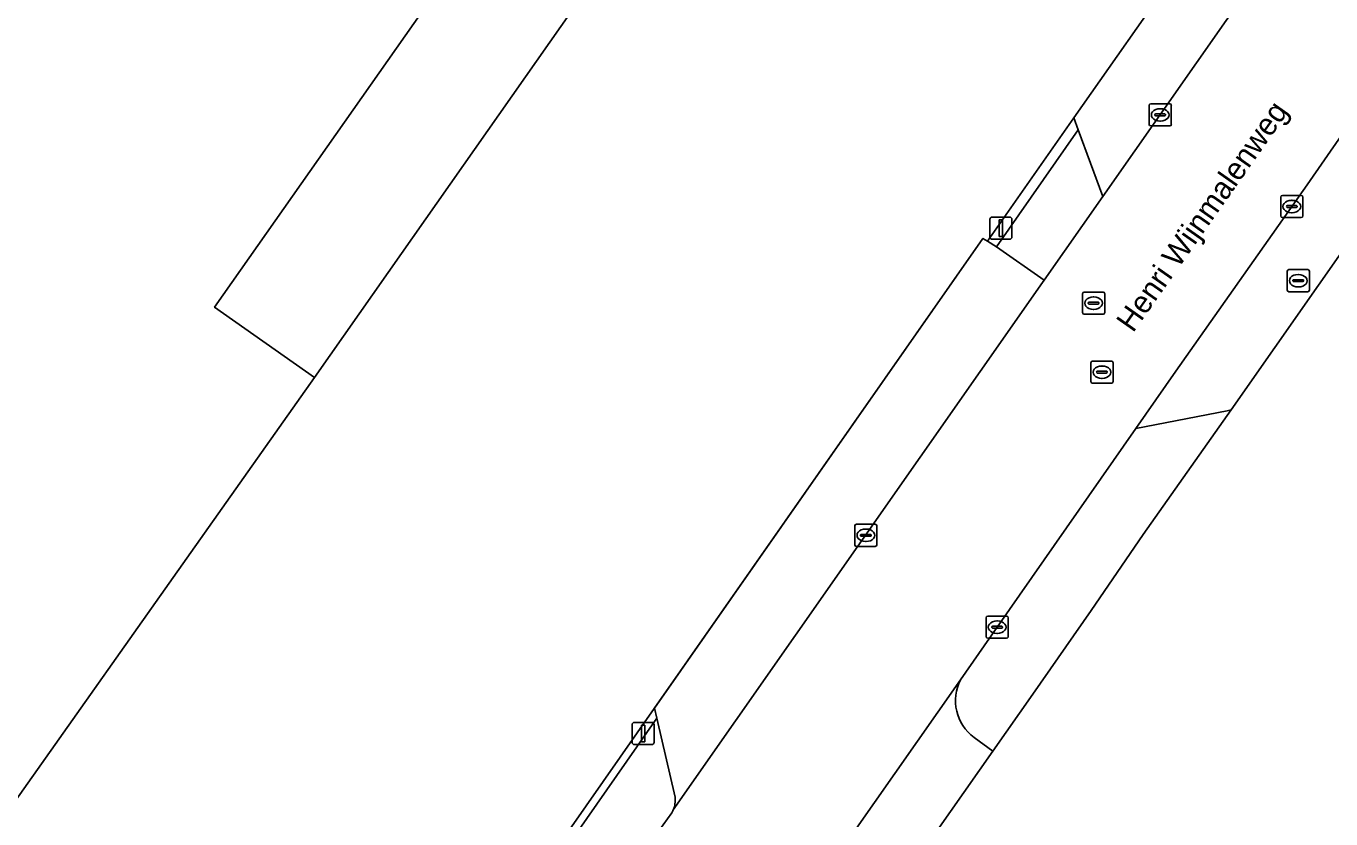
# Model space of a CAD drawing. Extents: x 155018 to 156648, y 383979 to 385733.
# Drawn here: x 155332.5 to 155391.5, y 384917.7 to 384953.5 of the extents above; entities that cross this region are included whole.
import ezdxf

# ---------------------------------------------------------------- set-up
doc = ezdxf.new("R2010")
doc.units = 0
for name, color, linetype in [('IMGEO_Brandkraan', 7, 'Continuous'), ('IMGEO_Erf', 7, 'Continuous'), ('IMGEO_Hek', 7, 'Continuous'), ('IMGEO_Kolk', 7, 'Continuous'), ('IMGEO_Lichtmast', 7, 'Continuous'), ('IMGEO_Openbare_ruimte_label', 7, 'Continuous'), ('IMGEO_Pand', 7, 'Continuous'), ('IMGEO_Pand_overbouw', 7, 'Continuous'), ('IMGEO_Parkeervlak_open', 7, 'Continuous'), ('IMGEO_Rijbaan_lokaal_gesloten', 7, 'Continuous'), ('IMGEO_Rijbaan_lokaal_open', 7, 'Continuous'), ('IMGEO_Rioolput', 7, 'Continuous'), ('IMGEO_Voetpad_open', 7, 'Continuous')]:
    doc.layers.add(name, color=color, linetype=linetype)

msp = doc.modelspace()

# ---------------------------------------------------------------- linework, layer by layer
at = {"layer": 'IMGEO_Brandkraan'}
for p, q in [((155389.49, 384941.613), (155389.49, 384942.465)), ((155389.565, 384942.539), (155390.417, 384942.539)), ((155389.978, 384942.319), (155390.003, 384942.319)), ((155390.491, 384942.465), (155390.491, 384941.613)), ((155390.417, 384941.539), (155389.565, 384941.539)), ((155389.749, 384942.033), (155389.749, 384942.045)), ((155390.187, 384941.996), (155389.789, 384941.996)), ((155389.792, 384942.082), (155390.19, 384942.082)), ((155390.001, 384941.759), (155389.976, 384941.759)), ((155390.233, 384942.045), (155390.233, 384942.033))]:
    msp.add_line(p, q, dxfattribs=at)
for points in [[(155389.49, 384941.613), (155389.49, 384942.465)], [(155389.565, 384942.539), (155390.417, 384942.539)], [(155390.491, 384942.465), (155390.491, 384941.613)], [(155390.417, 384941.539), (155389.565, 384941.539)]]:
    msp.add_lwpolyline(points, dxfattribs=at)
for centre, radius, start, end in [((155389.567, 384942.463), 0.0765, 91.55205, 178.44795), ((155389.567, 384942.463), 0.0765, 91.55205, 178.44795), ((155390.415, 384942.463), 0.0765, 1.55205, 88.44795), ((155390.415, 384942.463), 0.0765, 1.55205, 88.44795), ((155389.567, 384941.615), 0.0765, 181.55205, 268.44795), ((155389.567, 384941.615), 0.0765, 181.55205, 268.44795), ((155389.789, 384942.042), 0.0403, 85.87752, 175.75265), ((155389.786, 384942.032), 0.0366, 178.93798, 274.71019), ((155390.19, 384942.039), 0.043, 264.86636, 352.45326), ((155390.194, 384942.044), 0.0386, 1.73085, 96.63898), ((155390.415, 384941.615), 0.0765, 271.55205, 358.44795), ((155390.415, 384941.615), 0.0765, 271.55205, 358.44795)]:
    msp.add_arc(centre, radius, start, end, dxfattribs=at)
for centre, major_axis, ratio, start_param, end_param in [((155389.977, 384942.039), (-0.387, 0.002), 0.722429, 4.712389, 7.853982), ((155390.002, 384942.039), (-0.39, 0.002), 0.717154, 1.570796, 4.712389)]:
    msp.add_ellipse(centre, major_axis=major_axis, ratio=ratio, start_param=start_param, end_param=end_param, dxfattribs=at)
at = {"layer": 'IMGEO_Erf'}
for points in [[(155435.235, 385005.097), (155431.663, 385000), (155395.301, 384948.119), (155392.871, 384944.656), (155386.964, 384936.206), (155382.993, 384930.585), (155380.633, 384927.147), (155378.001, 384923.366), (155376.2, 384920.796), (155354.955, 384890.532), (155337.874, 384866.058)], [(155327.011, 384874.232), (155360.91, 384922.726), (155360.915, 384922.733), (155375.747, 384943.951), (155375.951, 384943.821), (155379.854, 384949.392), (155384.652, 384956.241), (155384.747, 384956.376), (155393.303, 384968.589), (155396.774, 384973.585), (155396.869, 384973.702), (155415.322, 385000)]]:
    msp.add_lwpolyline(points, dxfattribs=at)
msp.add_lwpolyline([(155357.905, 384955.275), (155357.454, 384954.61), (155357.294, 384954.376), (155352.785, 384957.566), (155341.057, 384940.844), (155345.564, 384937.674), (155326.662, 384910.934), (155325.533, 384911.727), (155312.836, 384894.014), (155265.219, 384927.444), (155268.309, 384932.073), (155267.067, 384932.914), (155247.386, 384946.755), (155287.947, 385004.428)], close=True, dxfattribs=at)
at = {"layer": 'IMGEO_Hek'}
for points in [[(155360.91, 384922.726), (155375.747, 384943.951)], [(155310.058, 384871.115), (155310.625, 384870.717), (155312.665, 384869.611), (155314.915, 384869.017), (155317.252, 384868.882), (155319.559, 384869.078), (155321.747, 384869.789), (155323.807, 384870.894), (155325.598, 384872.375), (155327.011, 384874.232), (155360.91, 384922.726)]]:
    msp.add_lwpolyline(points, dxfattribs=at)
at = {"layer": 'IMGEO_Kolk'}
for p, q in [((155383.256, 384949.099), (155383.256, 384949.951)), ((155383.331, 384950.025), (155384.183, 384950.025)), ((155383.744, 384949.805), (155383.769, 384949.805)), ((155384.257, 384949.951), (155384.257, 384949.099)), ((155383.515, 384949.519), (155383.515, 384949.531)), ((155383.953, 384949.482), (155383.555, 384949.482)), ((155383.558, 384949.568), (155383.956, 384949.568)), ((155383.767, 384949.245), (155383.742, 384949.245)), ((155383.999, 384949.531), (155383.999, 384949.519)), ((155384.183, 384949.025), (155383.331, 384949.025)), ((155389.197, 384944.962), (155389.197, 384945.814)), ((155389.272, 384945.888), (155390.124, 384945.888)), ((155389.685, 384945.668), (155389.71, 384945.668)), ((155390.198, 384945.814), (155390.198, 384944.962)), ((155389.456, 384945.382), (155389.456, 384945.394)), ((155389.894, 384945.345), (155389.496, 384945.345)), ((155389.499, 384945.431), (155389.897, 384945.431)), ((155389.708, 384945.108), (155389.683, 384945.108)), ((155389.94, 384945.394), (155389.94, 384945.382)), ((155390.124, 384944.888), (155389.272, 384944.888)), ((155369.964, 384930.118), (155369.964, 384930.97)), ((155370.039, 384931.044), (155370.891, 384931.044)), ((155370.965, 384930.97), (155370.965, 384930.118)), ((155370.223, 384930.538), (155370.223, 384930.55)), ((155370.661, 384930.501), (155370.263, 384930.501)), ((155370.266, 384930.587), (155370.664, 384930.587)), ((155370.452, 384930.824), (155370.477, 384930.824)), ((155370.707, 384930.55), (155370.707, 384930.538)), ((155370.891, 384930.044), (155370.039, 384930.044)), ((155370.475, 384930.264), (155370.45, 384930.264)), ((155375.893, 384925.969), (155375.893, 384926.821)), ((155375.968, 384926.895), (155376.82, 384926.895)), ((155376.894, 384926.821), (155376.894, 384925.969)), ((155376.152, 384926.389), (155376.152, 384926.401)), ((155376.59, 384926.352), (155376.192, 384926.352)), ((155376.195, 384926.438), (155376.593, 384926.438)), ((155376.381, 384926.675), (155376.406, 384926.675)), ((155376.636, 384926.401), (155376.636, 384926.389)), ((155376.82, 384925.895), (155375.968, 384925.895)), ((155376.404, 384926.115), (155376.379, 384926.115))]:
    msp.add_line(p, q, dxfattribs=at)
for points in [[(155383.256, 384949.099), (155383.256, 384949.951)], [(155383.331, 384950.025), (155384.183, 384950.025)], [(155384.257, 384949.951), (155384.257, 384949.099)], [(155384.183, 384949.025), (155383.331, 384949.025)], [(155389.197, 384944.962), (155389.197, 384945.814)], [(155389.272, 384945.888), (155390.124, 384945.888)], [(155390.198, 384945.814), (155390.198, 384944.962)], [(155390.124, 384944.888), (155389.272, 384944.888)], [(155369.964, 384930.118), (155369.964, 384930.97)], [(155370.039, 384931.044), (155370.891, 384931.044)], [(155370.965, 384930.97), (155370.965, 384930.118)], [(155370.891, 384930.044), (155370.039, 384930.044)], [(155375.893, 384925.969), (155375.893, 384926.821)], [(155375.968, 384926.895), (155376.82, 384926.895)], [(155376.894, 384926.821), (155376.894, 384925.969)], [(155376.82, 384925.895), (155375.968, 384925.895)]]:
    msp.add_lwpolyline(points, dxfattribs=at)
for centre, radius, start, end in [((155383.333, 384949.949), 0.0765, 91.55205, 178.44795), ((155383.333, 384949.949), 0.0765, 91.55205, 178.44795), ((155384.181, 384949.949), 0.0765, 1.55205, 88.44795), ((155384.181, 384949.949), 0.0765, 1.55205, 88.44795), ((155383.555, 384949.528), 0.0403, 85.87752, 175.75265), ((155383.552, 384949.518), 0.0366, 178.93798, 274.71019), ((155383.956, 384949.525), 0.043, 264.86636, 352.45326), ((155383.96, 384949.53), 0.0386, 1.73085, 96.63898), ((155383.333, 384949.101), 0.0765, 181.55205, 268.44795), ((155383.333, 384949.101), 0.0765, 181.55205, 268.44795), ((155384.181, 384949.101), 0.0765, 271.55205, 358.44795), ((155384.181, 384949.101), 0.0765, 271.55205, 358.44795), ((155389.274, 384945.812), 0.0765, 91.55205, 178.44795), ((155389.274, 384945.812), 0.0765, 91.55205, 178.44795), ((155390.122, 384945.812), 0.0765, 1.55205, 88.44795), ((155390.122, 384945.812), 0.0765, 1.55205, 88.44795), ((155389.496, 384945.391), 0.0403, 85.87752, 175.75265), ((155389.493, 384945.381), 0.0366, 178.93798, 274.71019), ((155389.897, 384945.388), 0.043, 264.86636, 352.45326), ((155389.901, 384945.393), 0.0386, 1.73085, 96.63898), ((155389.274, 384944.964), 0.0765, 181.55205, 268.44795), ((155389.274, 384944.964), 0.0765, 181.55205, 268.44795), ((155390.122, 384944.964), 0.0765, 271.55205, 358.44795), ((155390.122, 384944.964), 0.0765, 271.55205, 358.44795), ((155370.041, 384930.968), 0.0765, 91.55205, 178.44795), ((155370.041, 384930.968), 0.0765, 91.55205, 178.44795), ((155370.889, 384930.968), 0.0765, 1.55205, 88.44795), ((155370.889, 384930.968), 0.0765, 1.55205, 88.44795), ((155370.263, 384930.547), 0.0403, 85.87752, 175.75265), ((155370.26, 384930.537), 0.0366, 178.93798, 274.71019), ((155370.664, 384930.544), 0.043, 264.86636, 352.45326), ((155370.668, 384930.549), 0.0386, 1.73085, 96.63898), ((155370.041, 384930.12), 0.0765, 181.55205, 268.44795), ((155370.041, 384930.12), 0.0765, 181.55205, 268.44795), ((155370.889, 384930.12), 0.0765, 271.55205, 358.44795), ((155370.889, 384930.12), 0.0765, 271.55205, 358.44795), ((155375.97, 384926.819), 0.0765, 91.55205, 178.44795), ((155375.97, 384926.819), 0.0765, 91.55205, 178.44795), ((155376.818, 384926.819), 0.0765, 1.55205, 88.44795), ((155376.818, 384926.819), 0.0765, 1.55205, 88.44795), ((155376.192, 384926.398), 0.0403, 85.87752, 175.75265), ((155376.189, 384926.388), 0.0366, 178.93798, 274.71019), ((155376.593, 384926.395), 0.043, 264.86636, 352.45326), ((155376.597, 384926.4), 0.0386, 1.73085, 96.63898), ((155375.97, 384925.971), 0.0765, 181.55205, 268.44795), ((155375.97, 384925.971), 0.0765, 181.55205, 268.44795), ((155376.818, 384925.971), 0.0765, 271.55205, 358.44795), ((155376.818, 384925.971), 0.0765, 271.55205, 358.44795)]:
    msp.add_arc(centre, radius, start, end, dxfattribs=at)
for centre, major_axis, ratio, start_param, end_param in [((155383.743, 384949.525), (-0.387, 0.002), 0.722429, 4.712389, 7.853982), ((155383.768, 384949.525), (-0.39, 0.002), 0.717154, 1.570796, 4.712389), ((155389.684, 384945.388), (-0.387, 0.002), 0.722429, 4.712389, 7.853982), ((155389.709, 384945.388), (-0.39, 0.002), 0.717154, 1.570796, 4.712389), ((155370.451, 384930.544), (-0.387, 0.002), 0.722429, 4.712389, 7.853982), ((155370.476, 384930.544), (-0.39, 0.002), 0.717154, 1.570796, 4.712389), ((155376.38, 384926.395), (-0.387, 0.002), 0.722429, 4.712389, 7.853982), ((155376.405, 384926.395), (-0.39, 0.002), 0.717154, 1.570796, 4.712389)]:
    msp.add_ellipse(centre, major_axis=major_axis, ratio=ratio, start_param=start_param, end_param=end_param, dxfattribs=at)
at = {"layer": 'IMGEO_Lichtmast'}
for p, q in [((155376.069, 384944.013), (155376.069, 384944.813)), ((155376.069, 384944.813), (155376.069, 384944.013)), ((155376.169, 384944.913), (155376.959, 384944.913)), ((155376.959, 384944.913), (155376.169, 384944.913)), ((155377.059, 384944.813), (155377.059, 384944.013)), ((155377.059, 384944.013), (155377.059, 384944.813)), ((155376.959, 384943.913), (155376.169, 384943.913)), ((155376.169, 384943.913), (155376.959, 384943.913)), ((155360.008, 384922.094), (155360.798, 384922.094)), ((155360.798, 384922.094), (155360.008, 384922.094)), ((155359.908, 384921.194), (155359.908, 384921.994)), ((155359.908, 384921.994), (155359.908, 384921.194)), ((155360.898, 384921.994), (155360.898, 384921.194)), ((155360.898, 384921.194), (155360.898, 384921.994)), ((155360.798, 384921.094), (155360.008, 384921.094)), ((155360.008, 384921.094), (155360.798, 384921.094))]:
    msp.add_line(p, q, dxfattribs=at)
for points in [[(155376.489, 384944.788), (155376.639, 384944.788), (155376.639, 384944.038), (155376.489, 384944.038), (155376.489, 384944.788)], [(155360.328, 384921.969), (155360.478, 384921.969), (155360.478, 384921.219), (155360.328, 384921.219), (155360.328, 384921.969)]]:
    msp.add_lwpolyline(points, dxfattribs=at)
for centre, start, end in [((155376.169, 384944.813), 90, 180), ((155376.169, 384944.813), 90, 180), ((155376.959, 384944.813), 0, 90), ((155376.959, 384944.813), 360, 90), ((155376.169, 384944.013), 180, 270), ((155376.169, 384944.013), 180, 270), ((155376.959, 384944.013), 270, 0), ((155376.959, 384944.013), 270, 0), ((155360.008, 384921.994), 90, 180), ((155360.008, 384921.994), 90, 180), ((155360.798, 384921.994), 0, 90), ((155360.798, 384921.994), 360, 90), ((155360.008, 384921.194), 180, 270), ((155360.008, 384921.194), 180, 270), ((155360.798, 384921.194), 270, 0), ((155360.798, 384921.194), 270, 0)]:
    msp.add_arc(centre, 0.1, start, end, dxfattribs=at)
at = {"layer": 'IMGEO_Pand'}
msp.add_lwpolyline([(155345.564, 384937.674), (155341.057, 384940.844), (155352.785, 384957.566), (155357.294, 384954.376), (155357.454, 384954.61), (155357.905, 384955.275), (155287.947, 385004.428), (155247.386, 384946.755), (155267.067, 384932.914), (155268.309, 384932.073), (155265.219, 384927.444), (155312.836, 384894.014), (155325.533, 384911.727), (155326.662, 384910.934)], close=True, dxfattribs=at)
at = {"layer": 'IMGEO_Pand_overbouw'}
msp.add_lwpolyline([(155357.294, 384954.376), (155352.785, 384957.566), (155341.057, 384940.844), (155345.564, 384937.674), (155348.887, 384942.406)], close=True, dxfattribs=at)
at = {"layer": 'IMGEO_Parkeervlak_open'}
msp.add_lwpolyline([(155381.158, 384945.842), (155380.055, 384948.845), (155376.357, 384943.561), (155378.515, 384942.069)], close=True, dxfattribs=at)
at = {"layer": 'IMGEO_Rijbaan_lokaal_gesloten'}
for points in [[(155425.852, 385009.637), (155425.671, 385009.382), (155419.101, 385000), (155399.323, 384971.769), (155395.806, 384966.749), (155388.41, 384956.193), (155388.176, 384955.859), (155381.158, 384945.842), (155378.515, 384942.069), (155378.441, 384941.964), (155361.769, 384918.146)], [(155384.463, 384937.948), (155390.393, 384946.374), (155394.958, 384952.938), (155397.073, 384955.962), (155427.929, 385000), (155432.193, 385006.088)], [(155335.772, 384868.426), (155351.337, 384890.637), (155374.735, 384924.025), (155376.395, 384926.394), (155382.657, 384935.362), (155384.463, 384937.948)], [(155361.702, 384918.008), (155360.722, 384916.662), (155360.676, 384916.596), (155330.069, 384872.85), (155329.2, 384871.59)]]:
    msp.add_lwpolyline(points, dxfattribs=at)
msp.add_arc((155360.751, 384918.555), 1.097, 330.09232, 338.11386, dxfattribs=at)
at = {"layer": 'IMGEO_Rijbaan_lokaal_open'}
for points in [[(155388.176, 384955.859), (155388.41, 384956.193), (155385.733, 384956.227), (155385.225, 384956.234), (155384.652, 384956.241), (155379.854, 384949.392), (155380.055, 384948.845), (155381.158, 384945.842)], [(155392.871, 384944.656), (155395.301, 384948.119), (155394.958, 384952.938), (155390.393, 384946.374), (155384.463, 384937.948), (155382.657, 384935.362), (155386.777, 384936.169), (155386.964, 384936.206)]]:
    msp.add_lwpolyline(points, close=True, dxfattribs=at)
for points in [[(155327.339, 384874.089), (155357.86, 384917.764), (155361.028, 384922.286), (155360.915, 384922.733), (155360.91, 384922.726), (155327.011, 384874.232), (155325.598, 384872.375), (155323.807, 384870.894), (155321.747, 384869.789), (155319.559, 384869.078), (155317.252, 384868.882), (155314.915, 384869.017), (155312.665, 384869.611), (155310.625, 384870.717), (155310.058, 384871.115), (155247.243, 384915.217), (155232.066, 384925.988), (155227.994, 384928.878), (155223.854, 384931.752), (155220.046, 384934.396), (155190.84, 384954.671)], [(155378.441, 384941.964), (155378.515, 384942.069), (155376.357, 384943.561), (155375.951, 384943.821), (155375.747, 384943.951), (155360.915, 384922.733), (155361.028, 384922.286), (155361.848, 384918.716)], [(155361.769, 384918.146), (155378.441, 384941.964)]]:
    msp.add_lwpolyline(points, dxfattribs=at)
msp.add_arc((155360.685, 384918.587), 1.17, 337.87908, 6.33947, dxfattribs=at)
at = {"layer": 'IMGEO_Rioolput'}
for p, q in [((155380.247, 384940.598), (155380.247, 384941.45)), ((155380.322, 384941.524), (155381.174, 384941.524)), ((155380.506, 384941.018), (155380.506, 384941.03)), ((155380.944, 384940.981), (155380.546, 384940.981)), ((155380.549, 384941.067), (155380.947, 384941.067)), ((155380.735, 384941.304), (155380.76, 384941.304)), ((155380.99, 384941.03), (155380.99, 384941.018)), ((155381.248, 384941.45), (155381.248, 384940.598)), ((155381.174, 384940.524), (155380.322, 384940.524)), ((155380.758, 384940.744), (155380.733, 384940.744)), ((155380.625, 384937.482), (155380.625, 384938.334)), ((155380.7, 384938.408), (155381.552, 384938.408)), ((155381.113, 384938.188), (155381.138, 384938.188)), ((155381.626, 384938.334), (155381.626, 384937.482)), ((155380.884, 384937.902), (155380.884, 384937.914)), ((155381.322, 384937.865), (155380.924, 384937.865)), ((155380.927, 384937.951), (155381.325, 384937.951)), ((155381.136, 384937.628), (155381.111, 384937.628)), ((155381.368, 384937.914), (155381.368, 384937.902)), ((155381.552, 384937.408), (155380.7, 384937.408))]:
    msp.add_line(p, q, dxfattribs=at)
for points in [[(155380.247, 384940.598), (155380.247, 384941.45)], [(155380.322, 384941.524), (155381.174, 384941.524)], [(155381.248, 384941.45), (155381.248, 384940.598)], [(155381.174, 384940.524), (155380.322, 384940.524)], [(155380.625, 384937.482), (155380.625, 384938.334)], [(155380.7, 384938.408), (155381.552, 384938.408)], [(155381.626, 384938.334), (155381.626, 384937.482)], [(155381.552, 384937.408), (155380.7, 384937.408)]]:
    msp.add_lwpolyline(points, dxfattribs=at)
for centre, radius, start, end in [((155380.324, 384941.448), 0.0765, 91.55205, 178.44795), ((155380.324, 384941.448), 0.0765, 91.55205, 178.44795), ((155380.546, 384941.027), 0.0403, 85.87752, 175.75265), ((155380.543, 384941.017), 0.0366, 178.93798, 274.71019), ((155380.947, 384941.024), 0.043, 264.86636, 352.45326), ((155380.951, 384941.029), 0.0386, 1.73085, 96.63898), ((155381.172, 384941.448), 0.0765, 1.55205, 88.44795), ((155381.172, 384941.448), 0.0765, 1.55205, 88.44795), ((155380.324, 384940.6), 0.0765, 181.55205, 268.44795), ((155380.324, 384940.6), 0.0765, 181.55205, 268.44795), ((155381.172, 384940.6), 0.0765, 271.55205, 358.44795), ((155381.172, 384940.6), 0.0765, 271.55205, 358.44795), ((155380.702, 384938.332), 0.0765, 91.55205, 178.44795), ((155380.702, 384938.332), 0.0765, 91.55205, 178.44795), ((155381.55, 384938.332), 0.0765, 1.55205, 88.44795), ((155381.55, 384938.332), 0.0765, 1.55205, 88.44795), ((155380.702, 384937.484), 0.0765, 181.55205, 268.44795), ((155380.702, 384937.484), 0.0765, 181.55205, 268.44795), ((155380.924, 384937.911), 0.0403, 85.87752, 175.75265), ((155380.921, 384937.901), 0.0366, 178.93798, 274.71019), ((155381.325, 384937.908), 0.043, 264.86636, 352.45326), ((155381.329, 384937.913), 0.0386, 1.73085, 96.63898), ((155381.55, 384937.484), 0.0765, 271.55205, 358.44795), ((155381.55, 384937.484), 0.0765, 271.55205, 358.44795)]:
    msp.add_arc(centre, radius, start, end, dxfattribs=at)
for centre, major_axis, ratio, start_param, end_param in [((155380.734, 384941.024), (-0.387, 0.002), 0.722429, 4.712389, 7.853982), ((155380.759, 384941.024), (-0.39, 0.002), 0.717154, 1.570796, 4.712389), ((155381.112, 384937.908), (-0.387, 0.002), 0.722429, 4.712389, 7.853982), ((155381.137, 384937.908), (-0.39, 0.002), 0.717154, 1.570796, 4.712389)]:
    msp.add_ellipse(centre, major_axis=major_axis, ratio=ratio, start_param=start_param, end_param=end_param, dxfattribs=at)
at = {"layer": 'IMGEO_Voetpad_open'}
msp.add_lwpolyline([(155376.357, 384943.561), (155380.055, 384948.845), (155379.854, 384949.392), (155375.951, 384943.821)], close=True, dxfattribs=at)
for points in [[(155382.993, 384930.585), (155386.964, 384936.206), (155386.777, 384936.169), (155382.657, 384935.362), (155376.395, 384926.394), (155374.735, 384924.025)], [(155375.347, 384921.418), (155376.2, 384920.796), (155378.001, 384923.366), (155380.633, 384927.147), (155382.993, 384930.585)], [(155374.735, 384924.025), (155351.337, 384890.637)], [(155361.848, 384918.716), (155361.028, 384922.286), (155357.86, 384917.764), (155327.339, 384874.089)], [(155354.157, 384891.124), (155354.955, 384890.532), (155376.2, 384920.796), (155375.347, 384921.418)], [(155360.676, 384916.596), (155360.722, 384916.662), (155361.702, 384918.008)]]:
    msp.add_lwpolyline(points, dxfattribs=at)
for centre, radius, start, end in [((155376.588, 384923.085), 2.078, 153.09387, 233.32836), ((155376.588, 384923.085), 2.078, 153.09387, 233.32836), ((155360.685, 384918.587), 1.17, 337.87908, 6.33947), ((155360.751, 384918.555), 1.097, 330.09232, 338.11386)]:
    msp.add_arc(centre, radius, start, end, dxfattribs=at)

# ---------------------------------------------------------------- texts
at = {"layer": 'IMGEO_Openbare_ruimte_label'}
msp.add_text('Henri Wijnmalenweg', height=1, rotation=54.89531, dxfattribs=at).set_placement((155382.527, 384939.655))

doc.saveas('drawing.dxf')
